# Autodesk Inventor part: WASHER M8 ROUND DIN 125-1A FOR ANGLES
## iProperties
Created: 2006-02
Part Number: WASHER M8 ROUND DIN 125-1A FOR ANGLES
Material: Steel, Mild
Description: M8 ROUND WASHER FOR ANGLES
Document SubType Name: Modeling
Standard: DIN 125
Designer: Andy Moles
Standards Organization: DIN
Language: en-US
Size Designation: A 8.4
Categories: <MemberInstance><Categories><Category DisplayName="Fasteners" InternalName="e4da775c-781d-43d5-af7c-5136215cf5a6" Mnemonic="FSTN"><Category DisplayName="Washers
Mass: 1.83162 g
Surface Area: 4.13936 cm^2
Volume: 0.233031 cm^3
Density: 7.86 g/cm^3
Author: Andy Moles
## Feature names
1. Body [Extrusion]
